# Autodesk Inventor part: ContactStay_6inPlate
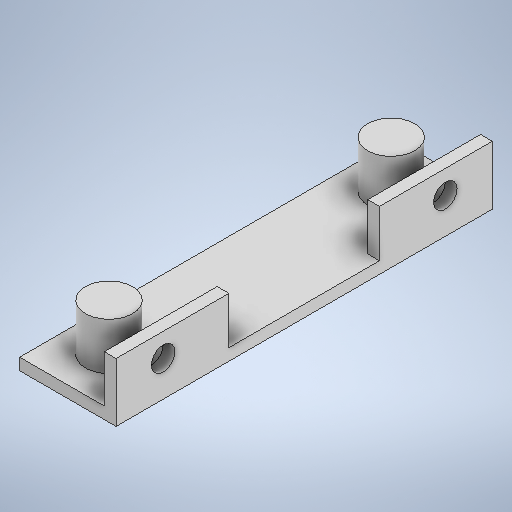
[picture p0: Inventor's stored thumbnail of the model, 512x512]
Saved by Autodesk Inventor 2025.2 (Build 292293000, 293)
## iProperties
Created: 2025-11
Part Number: ContactStay_6inPlate
Material: Generic
Document SubType Name: Modeling
Designer: tyler
Density: 1 g/cm^3
Appearance: Default
Author: tyler
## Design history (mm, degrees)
sketch "Sketch1"
  geometry: L1 (5.715, -25.4)-(-5.715, -25.4); L2 (-5.715, -25.4)-(-5.715, 25.4); L3 (-5.715, 25.4)-(5.715, 25.4); L4 (5.715, 25.4)-(5.715, -25.4); L5 (5.715, -25.4)-(-5.715, 25.4); L6 (-5.715, -25.4)-(5.715, 25.4); 1 further point
  constraints: 12 end point, 2 midpoint, 2 parallel, 1 horizontal, 1 perpendicular
  dimensions: "d0" = 50.8 distance of L3.end L1.start; "d1" = 11.43 distance of L2.end L3.end
extrude "Extrusion1" new body sketch "Sketch1" distance "d2" = 1.5875; taper "d3" = 0 deg
sketch "Sketch2"
  geometry: L1 (0, 0)-(0, -19.05); L2 (0, 0)-(0, 19.05); C1 r 3.175 at (0, -19.05); C2 r 3.175 at (0, 19.05)
  constraints: 4 end point, 2 centre point, 2 coincident, 2 vertical
  dimensions: "d4" = 19.05 distance of L1.start L1.end; "d5" = 19.05 distance of L1.start L2.end; "d6" = 6.35 diameter of C1; "d7" = 6.35 diameter of C2
extrude "Extrusion2" join sketch "Sketch2" distance "d8" = 6.35; taper "d9" = 0 deg
sketch "Sketch3"
  geometry: L1 (0, 0)-(0, 1.587) reference; L2 (0, 0)-(50.8, 0); L3 (50.8, 0)-(50.8, 7.938); L4 (50.8, 7.938)-(0, 7.938); L5 (0, 7.938)-(0, 0); L6 (25.4, 4.763)-(6.35, 4.763); L7 (25.4, 4.763)-(44.45, 4.763); L8 (25.4, 7.938)-(25.4, 4.763); C1 r 1.587 at (6.35, 4.763); C2 r 1.588 at (44.45, 4.763); 2 further points
  constraints: 14 end point, 3 horizontal, 2 centre point, 2 coincident, 2 parallel, 1 midpoint, 1 perpendicular, 1 vertical
  dimensions: "d10" = 50.8 distance of L4.end L3.end; "d11" = 7.9375 distance of L3.end L2.end; "d12" = 19.05 distance of L6.start L6.end; "d13" = 19.05 distance of L6.start L7.end; "d14" = 3.175 diameter of C1; "d15" = 3.175 diameter of C2; "d18" = 3.175 distance of L8.start L6.start
extrude "Extrusion3" join sketch "Sketch3" distance "d16" = 1.5875; taper "d17" = 0 deg
sketch "Sketch4"
  geometry: L1 (50.8, 7.938)-(0, 7.938) reference; L2 (25.4, 7.938)-(15.24, 7.938); L3 (15.24, 7.938)-(15.24, 1.587); L4 (15.24, 1.587)-(35.56, 1.588); L5 (35.56, 1.588)-(35.56, 7.938); L6 (35.56, 7.938)-(25.4, 7.938); 1 further point
  constraints: 10 end point, 3 perpendicular, 2 point on line, 1 horizontal, 1 midpoint
  dimensions: "d19" = 10.16 distance of L2.start L2.end; "d20" = 6.35 distance of L2.end L3.end; "d21" = 20.32 distance of L3.end L4.end
extrude "Extrusion4" cut sketch "Sketch4" distance "d22" = 6.35; taper "d23" = 0 deg
body "Solid1"
